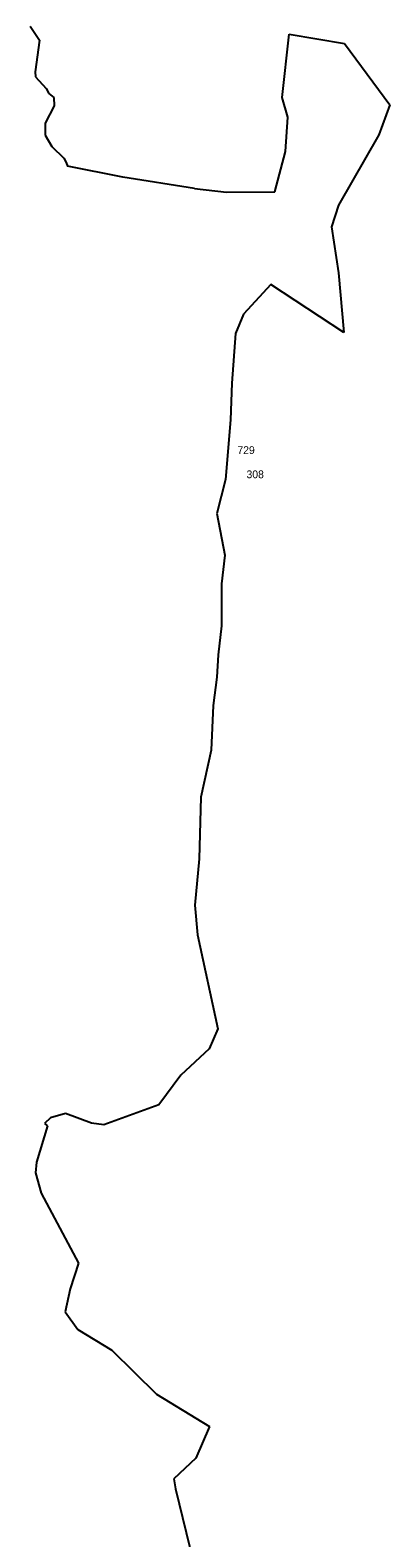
# Model space of a CAD drawing. Extents: x -782977 to -778030, y -975420 to -964838.
# Drawn here: x -782814 to -782494, y -967487 to -966146 of the extents above; entities that cross this region are included whole.
import ezdxf

# ---------------------------------------------------------------- set-up
doc = ezdxf.new("R2010")
doc.units = 0
doc.layers.add('Vrstva 13', color=7, linetype='Continuous')
doc.layers.add('Vrstva 24', color=7, linetype='Continuous')

msp = doc.modelspace()

# ---------------------------------------------------------------- linework, layer by layer
at = {"layer": 'Vrstva 13'}
for p, q in [((-782813.6, -966142.27), (-782805.26, -966154.48)), ((-782805.26, -966154.48), (-782809.31, -966182.67)), ((-782589.71, -966205.64), (-782583.52, -966149.15)), ((-782583.52, -966149.15), (-782534.14, -966157.48)), ((-782534.14, -966157.48), (-782493.97, -966212.03)), ((-782809.31, -966182.67), (-782808.73, -966187.16)), ((-782808.73, -966187.16), (-782799.52, -966197.7)), ((-782799.52, -966197.7), (-782796.88, -966202.17)), ((-782796.88, -966202.17), (-782792.71, -966205.53)), ((-782792.2, -966212.95), (-782800.23, -966228.41)), ((-782792.71, -966205.53), (-782792.2, -966212.95)), ((-782584.57, -966223.23), (-782589.71, -966205.64)), ((-782493.97, -966212.03), (-782503.8, -966238.74)), ((-782800.23, -966228.41), (-782800.14, -966239.18)), ((-782586.69, -966253.77), (-782584.57, -966223.23)), ((-782800.14, -966239.18), (-782794.24, -966249.35)), ((-782503.8, -966238.74), (-782539.51, -966301.27)), ((-782794.24, -966249.35), (-782783.77, -966259.52)), ((-782596.31, -966289.45), (-782586.69, -966253.77)), ((-782783.77, -966259.52), (-782781.64, -966263.58)), ((-782781.64, -966263.58), (-782780.44, -966266.61)), ((-782731.24, -966276.5), (-782780.44, -966266.61)), ((-782667.62, -966286.53), (-782731.24, -966276.5)), ((-782667.62, -966286.53), (-782639.08, -966289.85)), ((-782639.08, -966289.85), (-782596.31, -966289.45)), ((-782539.51, -966301.27), (-782545.83, -966320.68)), ((-782545.83, -966320.68), (-782539.72, -966361.66)), ((-782539.72, -966361.66), (-782534.76, -966414.63)), ((-782599.8, -966371.97), (-782623.98, -966398.49)), ((-782534.76, -966414.63), (-782599.8, -966371.97)), ((-782623.98, -966398.49), (-782631, -966415.62)), ((-782631, -966415.62), (-782634.3, -966459.85)), ((-782634.3, -966459.85), (-782635.51, -966492.45)), ((-782635.51, -966492.45), (-782639.96, -966545.44)), ((-782639.96, -966545.44), (-782647.81, -966575.61)), ((-782647.81, -966575.61), (-782640.7, -966612.75)), ((-782640.7, -966612.75), (-782643.58, -966638.28)), ((-782643.58, -966638.28), (-782643.68, -966675.69)), ((-782643.68, -966675.69), (-782646.59, -966701.33)), ((-782646.59, -966701.33), (-782647.64, -966721.23)), ((-782647.64, -966721.23), (-782650.87, -966746.63)), ((-782650.87, -966746.63), (-782652.65, -966786.11)), ((-782652.65, -966786.11), (-782661.95, -966828.12)), ((-782661.95, -966828.12), (-782663.41, -966882.89)), ((-782663.41, -966882.89), (-782667.37, -966924.07)), ((-782667.37, -966924.07), (-782664.94, -966950.44)), ((-782664.94, -966950.44), (-782646.94, -967034.12)), ((-782646.94, -967034.12), (-782654.38, -967051.96)), ((-782654.38, -967051.96), (-782679.65, -967075.22)), ((-782679.65, -967075.22), (-782699.22, -967101.88)), ((-782795.52, -967113.3), (-782800.86, -967118.32)), ((-782782.12, -967109.33), (-782795.52, -967113.3)), ((-782759.23, -967117.95), (-782782.12, -967109.33)), ((-782699.22, -967101.88), (-782748.03, -967119.56)), ((-782798.11, -967120.5), (-782808.13, -967152.71)), ((-782800.86, -967118.32), (-782798.11, -967120.5)), ((-782748.03, -967119.56), (-782759.23, -967117.95)), ((-782808.13, -967152.71), (-782808.94, -967162.33)), ((-782808.94, -967162.33), (-782803.93, -967180.38)), ((-782803.93, -967180.38), (-782770.78, -967242.5)), ((-782770.78, -967242.5), (-782777.99, -967265.31)), ((-782777.99, -967265.31), (-782782.43, -967285.9)), ((-782782.43, -967285.9), (-782771.24, -967301.69)), ((-782771.24, -967301.69), (-782740.94, -967320.13)), ((-782740.94, -967320.13), (-782701.44, -967359.05)), ((-782701.44, -967359.05), (-782654.09, -967387.84)), ((-782654.09, -967387.84), (-782666.43, -967416)), ((-782666.43, -967416), (-782685.96, -967434.49)), ((-782685.96, -967434.49), (-782684.35, -967443.47)), ((-782684.35, -967443.47), (-782668.66, -967507.59))]:
    msp.add_line(p, q, dxfattribs=at)

# ---------------------------------------------------------------- texts
at = {"layer": 'Vrstva 24'}
for s, p in [('729', (-782629.425, -966522.772)), ('308', (-782621.334, -966544.312))]:
    msp.add_text(s, height=6.912, dxfattribs=at).set_placement(p)

doc.saveas('drawing.dxf')
